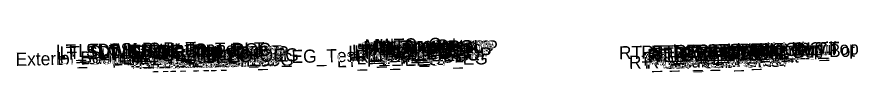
# Model space of a CAD drawing. Extents: x 118 to 4243, y 0 to 9511.
# Drawn here: x 1131 to 1260.3, y 1999.8 to 2005.1 of the extents above; entities that cross this region are included whole.
import ezdxf

# ---------------------------------------------------------------- set-up
doc = ezdxf.new("R2010")
doc.units = 0
doc.layers.add('Scratch_Level_0', color=7, linetype='Continuous')

msp = doc.modelspace()

# ---------------------------------------------------------------- texts
at = {"layer": 'Scratch_Level_0'}
for s, p in [('MI_Face Out', (1184.28, 2002.59)), ('MI_Top Out', (1184.49, 2002.86)), ('MI_Top In', (1185.63, 2002.61)), ('RT_PV1_PGL', (1185.75, 2002.45)), ('MI_Crown', (1186.09, 2002.9)), ('LT_SDWK_Out_Top', (1137.01, 2002.04)), ('LT_SDWK_Out_Bot', (1137.04, 2001.71)), ('LT_Sub_Trench_Out_DLT', (1137.57, 2001.79)), ('LT_CSLP_Pnt', (1140.44, 2002.12)), ('LT_SDWK_In_Top', (1143.63, 2001.97)), ('LT_SDWK_In_Bot', (1143.66, 2001.64)), ('LT_PV_Sub_Tie_Out', (1147.23, 2000.96)), ('LT_CG_Top_Face', (1147.53, 2001.87)), ('LT_CG_Top_BOC', (1148.05, 2001.89)), ('LT_CG_Top_Gut', (1148.51, 2001.39)), ('LT_PV_OEEOP_EG', (1149.82, 2001.01)), ('LT_PV2_OEEOP', (1151.58, 2001.28)), ('LT_PV1_OEEOP', (1152.15, 2001.42)), ('LT_PV2_OEOT', (1152.45, 2001.3)), ('LT_PV1_OEOT', (1153.01, 2001.56)), ('LT_PV_EG_TestPt', (1163.56, 2001.03)), ('LT_PV2_IEEOP', (1181.97, 2001.89)), ('LT_PV3_IEEOP', (1181.97, 2001.56)), ('LT_PV1_IEEOP', (1182.54, 2002.03)), ('LT_PV2_PGL1', (1182.9, 2001.91)), ('LT_PV3_PGL1', (1182.9, 2001.57)), ('RT_Sub_OEEOP', (1183.19, 2001.24)), ('LT_PV2_PGL', (1183.23, 2001.91)), ('LT_PV3_PGL', (1183.23, 2001.58)), ('RT_PV2_OEEOP', (1183.28, 2002.16)), ('RT_PV3_OEEOP', (1183.28, 2001.82)), ('LT_PV1_PGL', (1183.8, 2002.18)), ('RT_PV1_OEEOP', (1183.85, 2002.29)), ('MI_Face In', (1183.92, 2002.34)), ('RT_PV2_IEEOP', (1183.93, 2002.17)), ('RT_PV1_IEEOP', (1184.49, 2002.3)), ('RT_PV2_PGL1', (1184.86, 2002.19)), ('RT_PV3_PGL1', (1184.86, 2001.85)), ('RT_PV2_PGL', (1185.19, 2002.19)), ('RT_PV4_PGL', (1185.19, 2001.28)), ('MI_Bot Out', (1185.28, 2002.45)), ('RT_Sub_Trench_Out_DLT', (1223.56, 2001.79)), ('RT_CG_Top_Face', (1226.99, 2001.87)), ('RT_PV2_OEOT', (1227.9, 2001.3)), ('RT_CG_Top_Gut', (1227.96, 2001.39)), ('RT_PV1_OEOT', (1228.46, 2001.56)), ('RT_CG_Top_BOC', (1228.51, 2001.89)), ('RT_SDWK_In_Top', (1232.08, 2001.97)), ('RT_SDWK_In_Bot', (1232.11, 2001.64)), ('Exterior Boundary', (1233.96, 2002.01)), ('RT_SDWK_Out_Top', (1235.46, 2002.04)), ('RT_SDWK_Out_Bot', (1235.49, 2001.71)), ('RT_Slope_Cut', (1239.41, 2002.12)), ('RT_Slope_Fill', (1240.29, 2002.14)), ('RT_Shld_O', (1241.81, 2002.16)), ('CSLP_Pnt', (1242.64, 2002.17)), ('Exterior Boundary', (1130.8, 2000.79)), ('LT_Slope_Fill', (1137.18, 2000.92)), ('LT_CG1_Shelf_Out', (1145.82, 2000.83)), ('LT_CG_Bot_BOC', (1148.09, 2000.88)), ('LT_Sub_OEOP', (1148.79, 2000.31)), ('LT_Sub_OEOT_CG', (1149.64, 2000.33)), ('LT_Sub_OEEOP', (1151.48, 2000.36)), ('LT_PV3_OEEOP', (1151.58, 2000.95)), ('LT_CG_Bot_IE', (1152.19, 2000.96)), ('LT_Sub_OEOT', (1152.35, 2000.38)), ('LT_PV3_OEOT', (1152.45, 2000.97)), ('LT_PV_IEEOP_EG', (1180.21, 2000.56)), ('LT_PV4_PGL', (1183.23, 2001)), ('RT_Sub_OEOT_CG', (1225.1, 2000.33)), ('RT_CG1_Shelf_Out', (1227.28, 2000.83)), ('RT_CG_Bot_IE', (1227.64, 2000.96)), ('RT_Sub_OEOT', (1227.8, 2000.38)), ('RT_PV3_OEOT', (1227.9, 2000.96)), ('RT_CG_Bot_BOC', (1228.54, 2000.88)), ('RT_Sub_OEOP', (1231.43, 2000.31))]:
    msp.add_text(s, height=2, rotation=1.1458, dxfattribs=at).set_placement(p)

doc.saveas('drawing.dxf')
